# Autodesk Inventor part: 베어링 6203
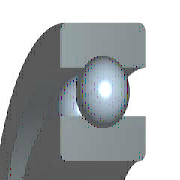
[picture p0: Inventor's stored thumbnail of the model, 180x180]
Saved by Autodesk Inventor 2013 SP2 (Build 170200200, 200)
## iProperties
IsCustomPart: 0
Created: 2016-04
Part Number: 베어링 6203
Material: 알루미늄 6061
Description: 깊은 그루브 볼 베어링
Document SubType Name: Modeling
Standard: KS B 2023
Designer: mdu
Standards Organization: KS
Language: ko-KR
Size Designation: 6203 - 17 x 40 x 12
Categories: <MemberInstance><Categories><Category DisplayName="샤프트 부품" InternalName="7f7aeb1f-a693-4053-b835-cee3144e0d98" Mnemonic="SHFT"><Category DisplayName="베어링" Inter
Density: 2.71 g/cm^3
Mass: 22.4044 g
Surface Area: 64.3582 cm^2
Volume: 8.26729 cm^3
Author: mdu
Revision Number: 1
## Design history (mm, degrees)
sketch "스케치" dims "d0" = 5.98 (= -0.26 x WD + 0.26 x BD)
  geometry: L1 (3.01, 14.25)-(8.99, 14.25); L2 (6, 14.25)-(6, 11.26); L3 (6, 14.25)-(6, 17.24); L4 (3.778, 12.249)-(0, 12.249); L5 (0, 8.5)-(12, 8.5); L6 (3.778, 16.251)-(0, 16.251); L7 (0, 20)-(12, 20); L8 (12, 8.5)-(12, 12.249); L9 (8.222, 12.249)-(12, 12.249); L10 (8.222, 16.251)-(12, 16.251); L11 (12, 20)-(12, 16.251); L12 (-1.4, 0)-(8.4, 0) reference; L13 (0, -0.3)-(0, 5.3) reference
  constraints: 22 end point, 4 point on line, 2 collinear, 2 perpendicular, 2 symmetric about line, 1 midpoint, 1 parallel, 14 other
  dimensions: "d9" = 17 diameter of L5 L12 (= WD); "d11" = 40 diameter of L7 L12 (= BD); "d12" = 12 distance between parallel lines of L8 L13 (= KB); "d13" = 24.498 diameter of L9 L12 (= 0.326 x BD + 0.674 x WD)
revolve "본체" stored, may be unused: angle "d6" = 90 deg
revolve "볼" stored, may be unused: angle "d7" = 90 deg
pattern_circular "IDS_ARRAYBALL[SIMPL:T]" dims angle "d3" = 360 deg
body "Solid1"
fillet "모깎기1" dims "d1" = 0.6 (= KRS)
other parameters: "WD" = 17 [user parameter; used in 5 equation terms], "BD" = 40 [user parameter; used in 5 equation terms], "KB" = 12 [user parameter; used in 1 equation term], "KRS" = 0.6 [user parameter; used in 1 equation term], "d4" = 0, "d5" = 0, "d8" = 0, "d14" = 0, "d15" = 0, "BBA" = 0 [user parameter], "BC0" = 4750000 [user parameter], "BC" = 9560000 [user parameter], "WR" = 8.5 (= 0.5 x WD) [user parameter]
